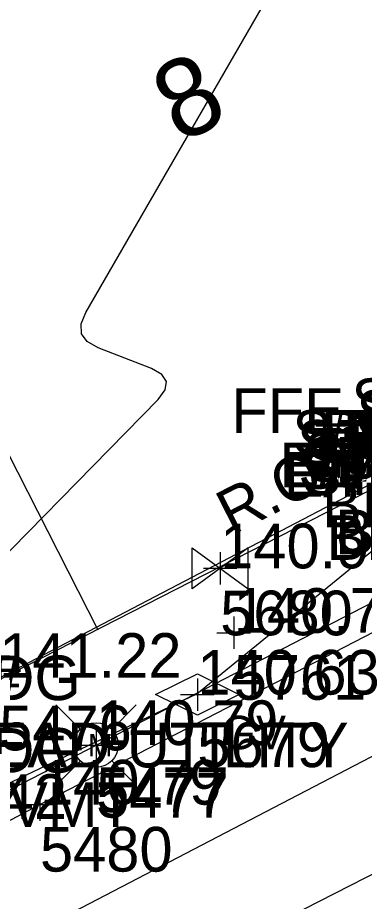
# Model space of a CAD drawing. Extents: x 13482495 to 13483389, y 311646 to 312209.
# Drawn here: x 13483113.1 to 13483138, y 312018.4 to 312081.7 of the extents above; entities that cross this region are included whole.
import ezdxf

# ---------------------------------------------------------------- set-up
doc = ezdxf.new("R2010")
doc.units = 0
for name, color, linetype in [('V-BLDG-IDEN', 7, 'Continuous'), ('V-BLDG-OTLN', 7, 'Continuous'), ('V-COMM-UNDR', 7, 'Continuous'), ('V-DOMW-MHOL', 7, 'Continuous'), ('V-NGAS-MAIN', 7, 'Continuous'), ('V-NGAS-MHOL', 7, 'Continuous'), ('V-PROP-IDEN', 7, 'Continuous'), ('V-PROP-LINE', 7, 'Continuous'), ('V-PROP-RWAY', 7, 'Continuous'), ('V-PROP-RWAY-IDEN', 7, 'Continuous'), ('V-PVMT-CNTR', 7, 'Continuous'), ('V-PVMT-ROAD', 7, 'Continuous'), ('V-PVMT-SPOT', 7, 'Continuous'), ('V-SITE-SPOT', 7, 'Continuous'), ('V-SURV-PNTS', 7, 'Continuous'), ('V-TOPO-LINE-IDEN', 7, 'Continuous'), ('V-TOPO-MINR', 7, 'Continuous'), ('V-TOPO-SPOT', 7, 'Continuous'), ('V-UTIL-OVHD', 7, 'Continuous'), ('V-UTIL-OVHD-DEMO', 7, 'Continuous'), ('V-UTIL-SPOT', 7, 'Continuous')]:
    doc.layers.add(name, color=color, linetype=linetype)

msp = doc.modelspace()

# ---------------------------------------------------------------- linework, layer by layer
at = {"layer": 'V-BLDG-OTLN'}
msp.add_lwpolyline([(13483111.744, 312034.374), (13483141.033, 312049.627), (13483141.656, 312050.033), (13483140.713, 312051.966), (13483144.951, 312054.231), (13483145.309, 312053.397), (13483145.304, 312053.353), (13483145.811, 312052.228), (13483146.525, 312052.272), (13483146.574, 312052.466), (13483163.758, 312061.272), (13483164.248, 312061.542), (13483164.25, 312061.753), (13483163.821, 312062.595), (13483163.771, 312062.661), (13483164.819, 312064.717), (13483166.586, 312064.922), (13483166.625, 312064.079), (13483166.621, 312063.963), (13483166.952, 312062.984), (13483167.593, 312063.142), (13483188.614, 312073.96), (13483178.694, 312093.211)], dxfattribs=at)
at = {"layer": 'V-COMM-UNDR'}
msp.add_lwpolyline([(13482638.43, 311773.216), (13482816.883, 311864.737), (13483031.639, 311973.194), (13483313.841, 312119.913)], dxfattribs=at)
at = {"layer": 'V-DOMW-MHOL'}
msp.add_lwpolyline([(13483125.607, 312043.701), (13483129.607, 312040.741), (13483129.607, 312043.701), (13483125.607, 312040.741), (13483125.607, 312043.701)], dxfattribs=at)
at = {"layer": 'V-NGAS-MAIN'}
msp.add_lwpolyline([(13482633.573, 311784.98), (13482635.758, 311786.099), (13483013.716, 311979.941), (13483125.923, 312033.234), (13483152.951, 312055.23), (13483267.213, 312112.659)], dxfattribs=at)
at = {"layer": 'V-NGAS-MHOL'}
for p, q in [((13483122.971, 312033.172), (13483125.971, 312034.652)), ((13483125.971, 312034.652), (13483128.971, 312033.172)), ((13483125.971, 312031.692), (13483122.971, 312033.172)), ((13483128.971, 312033.172), (13483125.971, 312031.692))]:
    msp.add_line(p, q, dxfattribs=at)
at = {"layer": 'V-PROP-LINE'}
msp.add_line((13483074.592, 312124.477), (13483118.826, 312037.818), dxfattribs=at)
at = {"layer": 'V-PROP-RWAY'}
msp.add_line((13482953.352, 311953.429), (13483318.617, 312139.792), dxfattribs=at)
at = {"layer": 'V-PVMT-CNTR'}
msp.add_lwpolyline([(13482583.662, 311737.164), (13482615.839, 311753.602), (13482631.764, 311761.327), (13482644.15, 311768.11), (13482660.198, 311776.177), (13482708.876, 311801.215), (13482756.857, 311825.709), (13482802.864, 311849.141), (13482850.908, 311873.114), (13482897.465, 311897.251), (13482945.27, 311921.454), (13482988.058, 311943.315), (13483031.887, 311965.625), (13483078.612, 311989.652), (13483123.69, 312012.726), (13483173.425, 312038.092), (13483222.972, 312063.092), (13483269.032, 312086.568), (13483297.768, 312101.095)], dxfattribs=at)
at = {"layer": 'V-PVMT-ROAD'}
msp.add_lwpolyline([(13483046.678, 311990.555), (13483079.211, 312006.888), (13483099.452, 312017.279), (13483114.671, 312025.287), (13483151.358, 312044.239), (13483167.233, 312052.433), (13483217.784, 312077.641), (13483241.711, 312089.928), (13483254.89, 312096.387), (13483267.926, 312103.062), (13483277.817, 312108.173), (13483290.977, 312115.044), (13483305.237, 312122.083), (13483309.354, 312124.167), (13483313.224, 312125.961), (13483313.468, 312125.194), (13483324.552, 312130.515), (13483328.35, 312132.225), (13483330.471, 312133.097), (13483331.734, 312133.829), (13483332.523, 312134.417), (13483333.988, 312135.742), (13483335.834, 312137.796), (13483336.653, 312138.925)], dxfattribs=at)
at = {"layer": 'V-PVMT-SPOT'}
for p, q in [((13483114.671, 312026.447), (13483114.671, 312024.127)), ((13483113.471, 312025.287), (13483115.871, 312025.287))]:
    msp.add_line(p, q, dxfattribs=at)
at = {"layer": 'V-TOPO-MINR'}
msp.add_lwpolyline([(13483100.947, 312031.717), (13483123.148, 312054.321), (13483123.658, 312055.009), (13483123.749, 312055.608), (13483123.421, 312056.117), (13483122.673, 312056.536), (13483118.843, 312058.032), (13483118.069, 312058.471), (13483117.664, 312059.038), (13483117.627, 312059.735), (13483117.957, 312060.56), (13483140.202, 312099.012)], dxfattribs=at)
at = {"layer": 'V-TOPO-SPOT'}
for p, q in [((13483128.577, 312038.761), (13483128.577, 312036.441)), ((13483127.377, 312037.601), (13483129.777, 312037.601))]:
    msp.add_line(p, q, dxfattribs=at)
at = {"layer": 'V-UTIL-OVHD'}
for p, q in [((13483117.58, 312030.674), (13483115.82, 312032.434)), ((13483119.82, 312030.674), (13483121.58, 312032.434)), ((13483115.78, 312026.634), (13483117.58, 312028.434)), ((13483121.5, 312026.754), (13483119.82, 312028.434))]:
    msp.add_line(p, q, dxfattribs=at)
msp.add_lwpolyline([(13483118.7, 312029.554), (13483287.396, 312116.623)], dxfattribs=at)
msp.add_circle((13483118.7, 312029.554), 1.6, dxfattribs=at)
at = {"layer": 'V-UTIL-OVHD-DEMO'}
msp.add_lwpolyline([(13482892.562, 311876.172), (13482977.709, 311956.604), (13483118.7, 312029.554)], dxfattribs=at)
at = {"layer": 'V-UTIL-SPOT'}
for p, q in [((13483127.607, 312043.381), (13483127.607, 312041.061)), ((13483126.407, 312042.221), (13483128.807, 312042.221)), ((13483125.971, 312034.332), (13483125.971, 312032.012)), ((13483124.771, 312033.172), (13483127.171, 312033.172)), ((13483118.7, 312030.714), (13483118.7, 312028.394)), ((13483118.7, 312030.714), (13483118.7, 312028.394)), ((13483117.5, 312029.554), (13483119.9, 312029.554)), ((13483117.5, 312029.554), (13483119.9, 312029.554))]:
    msp.add_line(p, q, dxfattribs=at)

# ---------------------------------------------------------------- texts
at = {"layer": 'V-BLDG-IDEN'}
msp.add_text('FFE 143.29', height=3.2, dxfattribs=at).set_placement((13483128.409, 312051.929))
at = {"layer": 'V-NGAS-MHOL'}
msp.add_text('GV', height=2.4, rotation=360, dxfattribs=at).set_placement((13483127.691, 312029.252))
at = {"layer": 'V-PROP-IDEN'}
msp.add_text('8', height=5.6, rotation=27.03125, dxfattribs=at).set_placement((13483124.713, 312072.601))
at = {"layer": 'V-PROP-RWAY-IDEN'}
msp.add_text('R.O.W. LINE', height=3.2, rotation=27.03125, dxfattribs=at).set_placement((13483128.452, 312044.564))
at = {"layer": 'V-PVMT-SPOT'}
msp.add_text('140.79', height=3.2, dxfattribs=at).set_placement((13483114.671, 312025.287))
at = {"layer": 'V-SITE-SPOT'}
msp.add_text('141.22', height=3.2, dxfattribs=at).set_placement((13483111.744, 312034.374))
at = {"layer": 'V-SURV-PNTS'}
for s, p in [('5680', (13483127.607, 312037.421)), ('5761', (13483128.577, 312032.801)), ('5476', (13483111.744, 312029.174)), ('5679', (13483125.971, 312027.972)), ('5477', (13483118.7, 312024.754)), ('5477', (13483118.7, 312024.354)), ('5480', (13483114.671, 312020.487))]:
    msp.add_text(s, height=3.2, dxfattribs=at).set_placement(p)
at = {"layer": 'V-TOPO-LINE-IDEN'}
for s, p in [('STAIRS', (13483137.027, 312052.631)), ('STAIRS', (13483137.379, 312051.753)), ('STAIRS', (13483137.385, 312051.797)), ('STAIRS', (13483132.788, 312050.366)), ('#1939', (13483134.338, 312050.366)), ('BLDG', (13483134.917, 312050.366)), ('STAIRS', (13483133.124, 312049.647)), ('STAIRS', (13483133.186, 312049.575)), ('STAIRS', (13483133.579, 312048.797)), ('E/PVMT', (13483131.85, 312048.027)), ('STAIRS', (13483133.732, 312048.433)), ('BLDG', (13483135.238, 312048.027)), ('BLDG', (13483135.861, 312048.433)), ('E/PVMT', (13483132.165, 312047.356)), ('STAIRS', (13483133.213, 312047.925)), ('STAIRS', (13483133.453, 312047.473)), ('BLDG', (13483134.917, 312045.166)), ('BLDG', (13483135.861, 312043.233)), ('BLDG', (13483135.238, 312042.827)), ('BLDG', (13483105.948, 312032.774)), ('#', (13483110.925, 312032.774)), ('OVERHEAD UTILITY', (13483095.696, 312027.954)), ('BLDG', (13483105.948, 312027.574)), ('E/PVMT', (13483105.487, 312023.687))]:
    msp.add_text(s, height=3.2, dxfattribs=at).set_placement(p)
at = {"layer": 'V-TOPO-SPOT'}
for s, p in [('140.76', (13483128.577, 312037.601)), ('141.42', (13483103.523, 312024.267))]:
    msp.add_text(s, height=3.2, dxfattribs=at).set_placement(p)
at = {"layer": 'V-UTIL-OVHD'}
msp.add_text('M', height=1.6, rotation=360, dxfattribs=at).set_placement((13483118.102, 312028.754))
at = {"layer": 'V-UTIL-SPOT'}
for s, p in [('140.98', (13483127.607, 312042.221)), ('140.63', (13483125.971, 312033.172)), ('140.79', (13483118.7, 312029.554)), ('140.79', (13483118.7, 312029.554))]:
    msp.add_text(s, height=3.2, dxfattribs=at).set_placement(p)

doc.saveas('drawing.dxf')
